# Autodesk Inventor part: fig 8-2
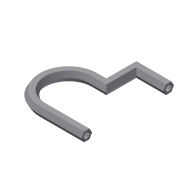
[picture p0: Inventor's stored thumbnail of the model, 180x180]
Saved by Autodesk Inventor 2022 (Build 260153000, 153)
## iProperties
Created: 2004-05
Part Number: fig 8-2
Document SubType Name: Modeling
Designer: CADCIM Technologies
Manufacturer: Standard
Standards Organization: Custom
Density: 1 g/cm^3
Material: Generic
Appearance: Default
Author: CADCIM Technologies
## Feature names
1. Sweep4
## Parameters: d3 = 0, d4 = 0
